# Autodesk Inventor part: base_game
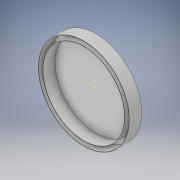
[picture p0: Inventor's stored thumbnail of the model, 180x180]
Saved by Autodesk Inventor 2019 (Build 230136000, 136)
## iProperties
Created: 2020-02
Part Number: base_game
Material: Generic
Document SubType Name: Modeling
Designer: Siddharth
Density: 1 g/cm^3
Appearance: Default
Author: Siddharth
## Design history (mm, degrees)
sketch "Sketch1"
  geometry: C1 r 304.8 at (0, 0); 1 further point
  constraints: 1 centre point, 1 coincident
  dimensions: "d0" = 609.6 diameter of C1
extrude "Extrusion1" new body sketch "Sketch1" distance "d1" = 2; taper "d2" = 0 deg
sketch "Sketch2"
  geometry: C1 r 302.3 at (0, 0); C2 r 304.8 at (0, 0); 1 further point
  constraints: 2 centre point, 2 coincident
  dimensions: "d3" = 604.6 diameter of C1; "d4" = 609.6 diameter of C2
extrude "Extrusion2" join sketch "Sketch2" distance "d5" = 80; taper "d6" = 0 deg
sketch "Sketch3"
  geometry: C1 r 274.8 at (0, 0); C2 r 272.3 at (0, 0); 1 further point
  constraints: 2 centre point, 2 coincident
  dimensions: "d7" = 549.6 diameter of C1; "d8" = 544.6 diameter of C2
extrude "Extrusion3" join sketch "Sketch3" distance "d9" = 80; taper "d10" = 0 deg
sketch "Sketch4"
  geometry: 1 further point
sketch "Sketch6"
  geometry: 1 further point
body "Solid1"
